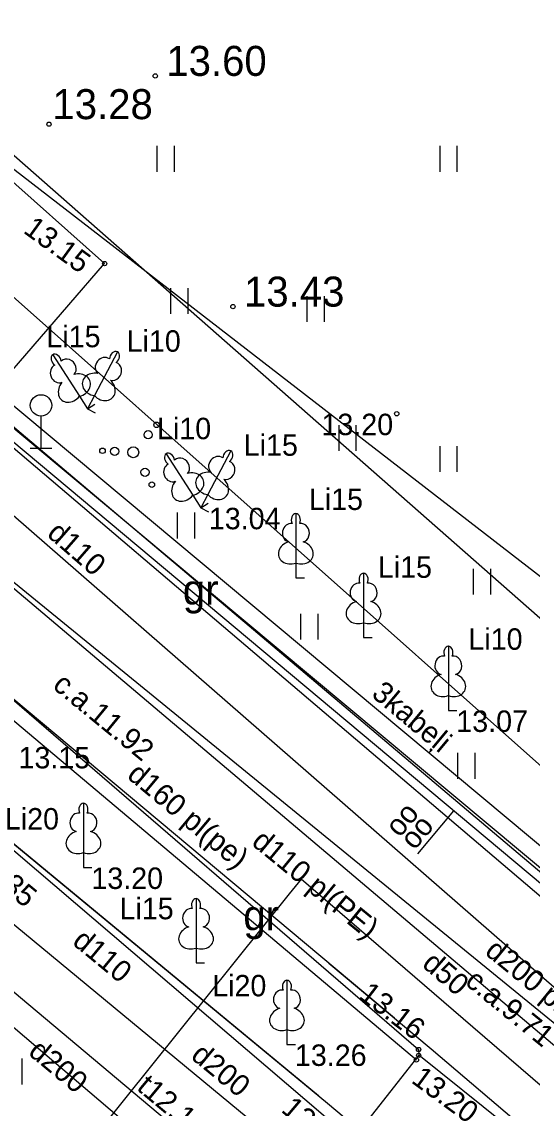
# Model space of a CAD drawing. Extents: x 503877 to 504025, y 304562 to 304725.
# Drawn here: x 503948.61 to 503960.53, y 304593.32 to 304618.66 of the extents above; entities that cross this region are included whole.
import ezdxf

# ---------------------------------------------------------------- set-up
doc = ezdxf.new("R2010")
doc.units = 0
for name, color, linetype in [('24', 7, 'Continuous'), ('25', 7, 'Continuous'), ('APGS_ACRL_####_####_#', 7, 'Continuous'), ('APGS_ACRL_####_TKST_#', 7, 'Continuous'), ('APGS_VADP_ZSPR_####_#', 7, 'Continuous'), ('APGS_VADP_ZSPR_TKST_#', 7, 'Continuous'), ('CELI_CMAL_####_####_#', 7, 'Continuous'), ('CELI_CSEG_####_TKST_#', 7, 'Continuous'), ('CELI_ELEM_####_####_#', 7, 'Continuous'), ('CELI_TAKA_####_####_#', 7, 'Continuous'), ('ELEK_VADV_ZSPR_####_#', 7, 'Continuous'), ('GAZE_VADP_VSP2_####_#', 7, 'Continuous'), ('GAZE_VADP_VSP2_TKST_#', 7, 'Continuous'), ('Level 46', 7, 'Continuous'), ('LKAN_VADP_PAST_####_#', 7, 'Continuous'), ('LKAN_VADP_PAST_TKST_#', 7, 'Continuous'), ('RELJ_AATZ_####_TKST_#', 7, 'Continuous'), ('RELJ_ELEM_####_####_#', 7, 'Continuous'), ('SAKK_IZVK_####_TKST_#', 7, 'Continuous'), ('SAKK_KKAN_####_####_#', 7, 'Continuous'), ('SAKK_KKAN_####_TKST_#', 7, 'Continuous'), ('SAKT_VADP_KABE_####_#', 7, 'Continuous'), ('SAKT_VADP_KABE_TKST_#', 7, 'Continuous'), ('SAKT_VADP_NEDR_####_#', 7, 'Continuous'), ('SKAN_VADP_PAST_####_#', 7, 'Continuous'), ('SKAN_VADP_PAST_####_I', 7, 'Continuous'), ('SKAN_VADP_PAST_TKST_#', 7, 'Continuous'), ('SKAN_VADP_PAST_TKST_I', 7, 'Continuous'), ('SKAN_VADP_SPDK_TKST_I', 7, 'Continuous'), ('TERT_DIAM_####_TKST_#', 7, 'Continuous'), ('TERT_ELEM_####_####_#', 7, 'Continuous'), ('UDTK_VADP_NEDR_####_#', 7, 'Continuous'), ('UDTK_VADP_NEDR_TKST_#', 7, 'Continuous'), ('UDTK_VADP_UDEN_####_#', 7, 'Continuous'), ('UDTK_VADP_UDEN_####_I', 7, 'Continuous'), ('UDTK_VADP_UDEN_TKST_I', 7, 'Continuous')]:
    doc.layers.add(name, color=color, linetype=linetype)

msp = doc.modelspace()

# ---------------------------------------------------------------- linework, layer by layer
at = {"layer": '24'}
msp.add_line((503960.823, 304605.633), (503933.144, 304627.024), dxfattribs=at)
at = {"layer": '25'}
msp.add_line((503924.947, 304625.297), (503985.325, 304574.255), dxfattribs=at)
at = {"layer": 'APGS_ACRL_####_####_#'}
msp.add_line((503955.54, 304593.612), (503947.7, 304600.079), dxfattribs=at)
at = {"layer": 'APGS_VADP_ZSPR_####_#'}
for p, q in [((503947.7, 304600.079), (503955.752, 304593.437)), ((503955.752, 304593.437), (503977.746, 304575.06))]:
    msp.add_line(p, q, dxfattribs=at)
at = {"layer": 'CELI_CMAL_####_####_#'}
for p, q in [((503950.55, 304613.018), (503942.522, 304620.157)), ((503947.498, 304609.501), (503950.55, 304613.018)), ((503962.594, 304596.657), (503947.498, 304609.501)), ((503944.692, 304606.054), (503957.877, 304594.69)), ((503956.326, 304592.583), (503942.956, 304603.993)), ((503954.372, 304590.15), (503943.33, 304599.524)), ((503957.88, 304594.554), (503956.326, 304592.583)), ((503957.877, 304594.69), (503957.88, 304594.554)), ((503959.9, 304592.938), (503957.88, 304594.554))]:
    msp.add_line(p, q, dxfattribs=at)
at = {"layer": 'CELI_ELEM_####_####_#'}
for p, q in [((503949.065, 304608.711), (503949.065, 304609.461)), ((503948.815, 304608.711), (503949.315, 304608.711))]:
    msp.add_line(p, q, dxfattribs=at)
msp.add_circle((503949.065, 304609.711), 0.25, dxfattribs=at)
at = {"layer": 'CELI_TAKA_####_####_#'}
for p, q in [((503947.74, 304609.79), (503962.913, 304596.977)), ((503944.42, 304605.72), (503957.828, 304594.446))]:
    msp.add_line(p, q, dxfattribs=at)
at = {"layer": 'ELEK_VADV_ZSPR_####_#'}
msp.add_line((503938.2, 304621.309), (503972.501, 304590.85), dxfattribs=at)
at = {"layer": 'GAZE_VADP_VSP2_####_#'}
for p, q in [((503939.829, 304610.045), (503957.313, 304595.425)), ((503955.782, 304596.704), (503958.172, 304594.706)), ((503958.172, 304594.706), (503971.829, 304583.093))]:
    msp.add_line(p, q, dxfattribs=at)
at = {"layer": 'Level 46'}
msp.add_line((503943.333, 304620.019), (504006.701, 304564.361), dxfattribs=at)
at = {"layer": 'LKAN_VADP_PAST_####_#'}
msp.add_line((503953.386, 304591.874), (503942.453, 304601.026), dxfattribs=at)
at = {"layer": 'RELJ_ELEM_####_####_#'}
for centre in [(503951.73, 304617.396), (503949.251, 304616.27), (503950.55, 304613.018), (503953.543, 304612.015), (503957.369, 304609.517), (503957.877, 304594.69), (503957.828, 304594.446), (503957.88, 304594.554)]:
    msp.add_circle(centre, 0.05, dxfattribs=at)
at = {"layer": 'SAKK_IZVK_####_TKST_#'}
msp.add_line((503958.693, 304600.256), (503957.851, 304599.25), dxfattribs=at)
at = {"layer": 'SAKK_KKAN_####_####_#'}
msp.add_line((503968.613, 304591.954), (503945.607, 304611.208), dxfattribs=at)
at = {"layer": 'SAKT_VADP_KABE_####_#'}
msp.add_line((503971.653, 304590.306), (503940.354, 304616.433), dxfattribs=at)
at = {"layer": 'SAKT_VADP_NEDR_####_#'}
msp.add_line((503997.217, 304568.475), (503924.507, 304629.123), dxfattribs=at)
at = {"layer": 'SKAN_VADP_PAST_####_#'}
msp.add_line((503971.339, 304578.696), (503938.881, 304605.476), dxfattribs=at)
at = {"layer": 'SKAN_VADP_PAST_####_I'}
msp.add_line((503973.287, 304585.319), (503945.224, 304608.195), dxfattribs=at)
at = {"layer": 'TERT_ELEM_####_####_#'}
for p, q in [((503951.779, 304615.162), (503951.779, 304615.762)), ((503952.179, 304615.162), (503952.179, 304615.762)), ((503958.379, 304615.162), (503958.379, 304615.762)), ((503958.779, 304615.162), (503958.779, 304615.762)), ((503952.097, 304611.847), (503952.097, 304612.447)), ((503952.497, 304611.847), (503952.497, 304612.447)), ((503955.279, 304611.662), (503955.279, 304612.262)), ((503955.679, 304611.662), (503955.679, 304612.262)), ((503949.962, 304609.924), (503950.15, 304609.632)), ((503950.311, 304609.939), (503950.15, 304609.632)), ((503950.15, 304609.632), (503950.318, 304609.74)), ((503950.15, 304609.632), (503950.327, 304609.539)), ((503956.021, 304608.652), (503956.021, 304609.252)), ((503956.421, 304608.652), (503956.421, 304609.252)), ((503958.379, 304608.162), (503958.379, 304608.762)), ((503958.779, 304608.162), (503958.779, 304608.762)), ((503952.957, 304607.63), (503952.796, 304607.323)), ((503952.608, 304607.615), (503952.796, 304607.323)), ((503952.796, 304607.323), (503952.964, 304607.431)), ((503952.254, 304606.61), (503952.254, 304607.21)), ((503952.654, 304606.61), (503952.654, 304607.21)), ((503952.796, 304607.323), (503952.973, 304607.23)), ((503955.013, 304606.035), (503955.013, 304605.688)), ((503959.161, 304605.301), (503959.161, 304605.901)), ((503959.561, 304605.301), (503959.561, 304605.901)), ((503955.013, 304605.688), (503955.213, 304605.688)), ((503955.132, 304604.253), (503955.132, 304604.853)), ((503955.532, 304604.253), (503955.532, 304604.853)), ((503956.594, 304604.643), (503956.594, 304604.296)), ((503956.594, 304604.296), (503956.794, 304604.296)), ((503958.572, 304602.943), (503958.572, 304602.596)), ((503958.572, 304602.596), (503958.772, 304602.596)), ((503958.795, 304601.006), (503958.795, 304601.606)), ((503959.195, 304601.006), (503959.195, 304601.606)), ((503950.054, 304599.281), (503950.054, 304598.934)), ((503950.054, 304598.934), (503950.254, 304598.934)), ((503952.683, 304597.055), (503952.683, 304596.708)), ((503952.683, 304596.708), (503952.883, 304596.708)), ((503954.805, 304595.154), (503954.805, 304594.807)), ((503954.805, 304594.807), (503955.005, 304594.807)), ((503948.625, 304593.876), (503948.625, 304594.476))]:
    msp.add_line(p, q, dxfattribs=at)
for points in [[(503950.848, 304610.96), (503950.311, 304609.939)], [(503949.338, 304610.893), (503949.962, 304609.924)], [(503949.539, 304610.746), (503949.538, 304610.747)], [(503950.819, 304610.712), (503950.818, 304610.714)], [(503953.494, 304608.651), (503952.957, 304607.63)], [(503951.984, 304608.584), (503952.608, 304607.615)], [(503952.185, 304608.437), (503952.184, 304608.438)], [(503953.465, 304608.403), (503953.464, 304608.405)], [(503955.013, 304607.188), (503955.013, 304606.035)], [(503955.103, 304606.956), (503955.102, 304606.957)], [(503956.594, 304605.796), (503956.594, 304604.643)], [(503956.684, 304605.564), (503956.683, 304605.565)], [(503958.572, 304604.096), (503958.572, 304602.943)], [(503958.662, 304603.864), (503958.661, 304603.865)], [(503950.054, 304600.434), (503950.054, 304599.281)], [(503950.144, 304600.202), (503950.143, 304600.203)], [(503952.683, 304598.208), (503952.683, 304597.055)], [(503952.773, 304597.976), (503952.772, 304597.977)], [(503954.805, 304596.307), (503954.805, 304595.154)], [(503954.895, 304596.075), (503954.894, 304596.076)]]:
    msp.add_lwpolyline(points, dxfattribs=at)
for centre, radius in [((503951.761, 304609.258), 0.064), ((503951.565, 304609.027), 0.096), ((503950.499, 304608.653), 0.064), ((503950.783, 304608.64), 0.096), ((503951.217, 304608.619), 0.128), ((503951.493, 304608.152), 0.096), ((503951.651, 304607.863), 0.064)]:
    msp.add_circle(centre, radius, dxfattribs=at)
for centre, major_axis, ratio, start_param, end_param in [((503950.778, 304610.827), (-0.07, -0.133), 0.707107, 3.14537, 5.287485), ((503950.778, 304610.827), (-0.07, -0.133), 0.707107, 0.995701, 3.137816), ((503949.42, 304610.767), (0.081, -0.126), 0.707107, 3.14537, 5.287485), ((503949.419, 304610.767), (0.081, -0.126), 0.707107, 0.995701, 3.137816), ((503949.687, 304610.589), (0.148, -0.158), 0.861323, 0, 3.141593), ((503950.527, 304610.626), (-0.133, -0.17), 0.861323, 3.141593, 6.283185), ((503950.754, 304610.506), (-0.065, -0.206), 0.861323, 0, 3.141593), ((503949.471, 304610.45), (0.082, -0.2), 0.861323, 3.141593, 6.283185), ((503949.904, 304610.179), (-0.309, -0.086), 0.814445, 1.531171, 4.712389), ((503950.346, 304610.199), (0.316, -0.059), 0.814445, 1.570796, 4.752015), ((503949.754, 304610.082), (0.206, 0.246), 0.814445, 1.570796, 4.752015), ((503950.505, 304610.115), (-0.227, 0.227), 0.814445, 1.531171, 4.712389), ((503953.424, 304608.518), (-0.07, -0.133), 0.707107, 3.14537, 5.287485), ((503953.424, 304608.518), (-0.07, -0.133), 0.707107, 0.995701, 3.137816), ((503952.066, 304608.458), (0.081, -0.126), 0.707107, 3.14537, 5.287485), ((503952.065, 304608.458), (0.081, -0.126), 0.707107, 0.995701, 3.137816), ((503952.333, 304608.28), (0.148, -0.158), 0.861323, 0, 3.141593), ((503953.173, 304608.317), (-0.133, -0.17), 0.861323, 3.141593, 6.283185), ((503953.4, 304608.197), (-0.065, -0.206), 0.861323, 0, 3.141593), ((503952.117, 304608.141), (0.082, -0.2), 0.861323, 3.141593, 6.283185), ((503952.55, 304607.87), (-0.309, -0.086), 0.814445, 1.531171, 4.712389), ((503952.992, 304607.89), (0.316, -0.059), 0.814445, 1.570796, 4.752015), ((503952.4, 304607.773), (0.206, 0.246), 0.814445, 1.570796, 4.752015), ((503953.151, 304607.806), (-0.227, 0.227), 0.814445, 1.531171, 4.712389), ((503955.013, 304607.038), (0, -0.15), 0.707107, 3.14537, 5.287485), ((503955.013, 304607.038), (0, -0.15), 0.707107, 0.995701, 3.137816), ((503954.885, 304606.743), (-0.039, -0.212), 0.861323, 3.141593, 6.283185), ((503955.141, 304606.743), (0.039, -0.212), 0.861323, 0, 3.141593), ((503954.923, 304606.281), (0.307, 0.095), 0.814445, 1.570796, 4.752015), ((503955.103, 304606.281), (-0.307, 0.095), 0.814445, 1.531171, 4.712389), ((503956.594, 304605.646), (0, -0.15), 0.707107, 3.14537, 5.287485), ((503956.594, 304605.646), (0, -0.15), 0.707107, 0.995701, 3.137816), ((503956.466, 304605.351), (-0.039, -0.212), 0.861323, 3.141593, 6.283185), ((503956.722, 304605.351), (0.039, -0.212), 0.861323, 0, 3.141593), ((503956.504, 304604.889), (0.307, 0.095), 0.814445, 1.570796, 4.752015), ((503956.684, 304604.889), (-0.307, 0.095), 0.814445, 1.531171, 4.712389), ((503958.572, 304603.946), (0, -0.15), 0.707107, 3.14537, 5.287485), ((503958.572, 304603.946), (0, -0.15), 0.707107, 0.995701, 3.137816), ((503958.444, 304603.651), (-0.039, -0.212), 0.861323, 3.141593, 6.283185), ((503958.7, 304603.651), (0.039, -0.212), 0.861323, 0, 3.141593), ((503958.482, 304603.189), (0.307, 0.095), 0.814445, 1.570796, 4.752015), ((503958.662, 304603.189), (-0.307, 0.095), 0.814445, 1.531171, 4.712389), ((503950.054, 304600.284), (0, -0.15), 0.707107, 3.14537, 5.287485), ((503950.054, 304600.284), (0, -0.15), 0.707107, 0.995701, 3.137816), ((503949.926, 304599.989), (-0.039, -0.212), 0.861323, 3.141593, 6.283185), ((503950.182, 304599.989), (0.039, -0.212), 0.861323, 0, 3.141593), ((503949.964, 304599.527), (0.307, 0.095), 0.814445, 1.570796, 4.752015), ((503950.144, 304599.527), (-0.307, 0.095), 0.814445, 1.531171, 4.712389), ((503952.683, 304598.058), (0, -0.15), 0.707107, 3.14537, 5.287485), ((503952.683, 304598.058), (0, -0.15), 0.707107, 0.995701, 3.137816), ((503952.555, 304597.763), (-0.039, -0.212), 0.861323, 3.141593, 6.283185), ((503952.811, 304597.763), (0.039, -0.212), 0.861323, 0, 3.141593), ((503952.593, 304597.301), (0.307, 0.095), 0.814445, 1.570796, 4.752015), ((503952.773, 304597.301), (-0.307, 0.095), 0.814445, 1.531171, 4.712389), ((503954.805, 304596.157), (0, -0.15), 0.707107, 3.14537, 5.287485), ((503954.805, 304596.157), (0, -0.15), 0.707107, 0.995701, 3.137816), ((503954.677, 304595.862), (-0.039, -0.212), 0.861323, 3.141593, 6.283185), ((503954.933, 304595.862), (0.039, -0.212), 0.861323, 0, 3.141593), ((503954.715, 304595.4), (0.307, 0.095), 0.814445, 1.570796, 4.752015), ((503954.895, 304595.4), (-0.307, 0.095), 0.814445, 1.531171, 4.712389)]:
    msp.add_ellipse(centre, major_axis=major_axis, ratio=ratio, start_param=start_param, end_param=end_param, dxfattribs=at)
at = {"layer": 'UDTK_VADP_NEDR_####_#'}
for p, q in [((503959.145, 304595.208), (503955.133, 304598.662)), ((503954.857, 304598.318), (503949.443, 304591.578)), ((503972.119, 304584.039), (503959.145, 304595.208))]:
    msp.add_line(p, q, dxfattribs=at)
at = {"layer": 'UDTK_VADP_UDEN_####_#'}
msp.add_line((503955.133, 304598.662), (503954.857, 304598.318), dxfattribs=at)
at = {"layer": 'UDTK_VADP_UDEN_####_I'}
msp.add_line((503942.658, 304612.162), (503968.511, 304589.634), dxfattribs=at)

# ---------------------------------------------------------------- texts
at = {"layer": 'APGS_ACRL_####_TKST_#'}
msp.add_text('d110', height=0.5, rotation=320.4812, dxfattribs=at).set_placement((503949.77, 304597.161))
at = {"layer": 'APGS_VADP_ZSPR_TKST_#'}
msp.add_text('AXPK 4x35', height=0.5, rotation=320.1197, dxfattribs=at).set_placement((503946.074, 304600.168))
at = {"layer": 'CELI_CSEG_####_TKST_#'}
for p in [(503952.375, 304605.065), (503953.788, 304597.47)]:
    msp.add_text('gr', height=0.7, dxfattribs=at).set_placement(p)
at = {"layer": 'GAZE_VADP_VSP2_TKST_#'}
msp.add_text('d160 pl(pe)', height=0.5, rotation=320.0979, dxfattribs=at).set_placement((503951.046, 304601.042))
at = {"layer": 'LKAN_VADP_PAST_TKST_#'}
for s, p in [('d200', (503948.742, 304594.589)), ('t12.18', (503951.273, 304593.767))]:
    msp.add_text(s, height=0.5, rotation=320.2454, dxfattribs=at).set_placement(p)
at = {"layer": 'RELJ_AATZ_####_TKST_#'}
for s, height, p in [(' 13.60', 0.7, (503951.73, 304617.396)), ('13.28', 0.7, (503949.331, 304616.387)), (' 13.43', 0.7, (503953.543, 304612.015)), (' 13.20', 0.5, (503955.425, 304609.017)), (' 13.04', 0.5, (503952.796, 304606.823)), (' 13.07', 0.5, (503958.572, 304602.096)), (' 13.15', 0.5, (503948.353, 304601.246)), (' 13.20', 0.5, (503950.054, 304598.434)), (' 13.26', 0.5, (503954.805, 304594.307))]:
    msp.add_text(s, height=height, dxfattribs=at).set_placement(p)
for s, rotation, p in [(' 13.15', 324.0249, (503948.477, 304613.862)), (' 13.16', 322.5721, (503956.307, 304596.019)), (' 13.20', 323.7822, (503957.533, 304594.043)), (' 13.19', 319.6269, (503954.505, 304593.375))]:
    msp.add_text(s, height=0.5, rotation=rotation, dxfattribs=at).set_placement(p)
at = {"layer": 'SAKK_KKAN_####_TKST_#'}
for p in [(503957.438, 304599.615), (503957.785, 304599.321)]:
    msp.add_text('oo', height=0.5, rotation=50.0624, dxfattribs=at).set_placement(p)
at = {"layer": 'SAKT_VADP_KABE_TKST_#'}
msp.add_text('3kabeļi', height=0.5, rotation=320.1464, dxfattribs=at).set_placement((503956.752, 304602.94))
at = {"layer": 'SKAN_VADP_PAST_TKST_#'}
msp.add_text('d200', height=0.5, rotation=320.4757, dxfattribs=at).set_placement((503952.536, 304594.498))
at = {"layer": 'SKAN_VADP_PAST_TKST_I'}
for s, p in [('d200 pl(PP)', (503959.399, 304596.929)), ('c.a.9.71', (503958.934, 304596.224))]:
    msp.add_text(s, height=0.5, rotation=320.8143, dxfattribs=at).set_placement(p)
at = {"layer": 'SKAN_VADP_SPDK_TKST_I'}
for s, p in [('c.a.11.92', (503949.309, 304603.133)), ('d110 pl(PE)', (503953.953, 304599.48))]:
    msp.add_text(s, height=0.5, rotation=320.6077, dxfattribs=at).set_placement(p)
at = {"layer": 'TERT_DIAM_####_TKST_#'}
for s, p in [('Li15', (503949.19, 304611.068)), ('Li10', (503951.062, 304610.963)), ('Li10', (503951.772, 304608.923)), ('Li15', (503953.797, 304608.536)), ('Li15', (503955.316, 304607.273)), ('Li15', (503956.926, 304605.69)), ('Li10', (503959.041, 304604.012)), ('Li20', (503948.22, 304599.82)), ('Li15', (503950.896, 304597.727)), ('Li20', (503953.06, 304595.929))]:
    msp.add_text(s, height=0.5, dxfattribs=at).set_placement(p)
at = {"layer": 'UDTK_VADP_NEDR_TKST_#'}
msp.add_text('d50', height=0.5, rotation=319.2766, dxfattribs=at).set_placement((503957.933, 304596.642))
at = {"layer": 'UDTK_VADP_UDEN_TKST_I'}
msp.add_text('d110', height=0.5, rotation=318.9315, dxfattribs=at).set_placement((503949.178, 304606.68))

doc.saveas('drawing.dxf')
